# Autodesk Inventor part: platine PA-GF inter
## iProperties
Created: 2011-07
Part Number: platine PA-GF inter
Document SubType Name: Modeling
Designer: Laur
Density: 1.13 g/cm^3
Material: Nylon - 6/6
Mass: 2.66326 g
Surface Area: 28.7081 cm^2
Volume: 2.35687 cm^3
Author: Laur
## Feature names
1. contour ext - ép 0,8 [Extrusion]
2. centrage int - ép 0,8 [Extrusion]
3. bossage1 fix capot [Extrusion]
4. alésage1 pour vis fix capot [Extrusion]
5. bossage loge carte [Extrusion]
6. bossage2 fix capot [Extrusion]
7. alésage2 pour vis fix capot [Extrusion]
8. bossage connect ph1 [Extrusion]
9. bossage connect ph2 [Extrusion]
10. bossage connect ph3 [Extrusion]
11. nervure connect à  loge carte [Extrusion]
12. bossage latéral loge carte [Extrusion]
13. évidemment bossage lat [Extrusion]
14. Extrusion17
15. Extrusion16
16. Extrusion18
17. Extrusion19
18. Congé1 [Fillet]
19. Extrusion20
20. Extrusion21
21. Congé2 [Fillet]
22. Extrusion22
23. Extrusion23
24. Extrusion24
25. Extrusion25
26. Extrusion26
